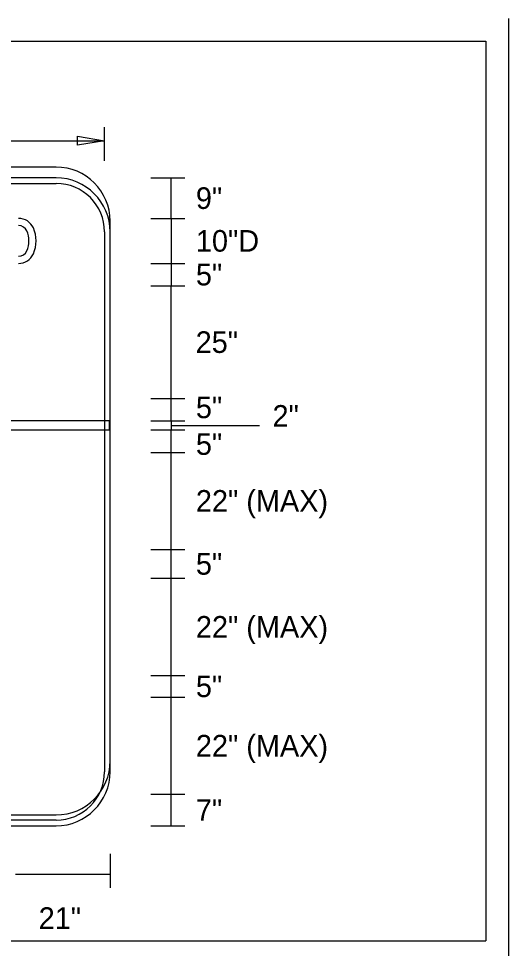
# Model space of a CAD drawing. Extents: x 10268259 to 10268554, y 2141099 to 2141249.
# Drawn here: x 10268378.4 to 10268394.73, y 2141173.28 to 2141204.28 of the extents above; entities that cross this region are included whole.
import ezdxf

# ---------------------------------------------------------------- set-up
doc = ezdxf.new("R2010")
doc.units = 0
for name, color, linetype in [('56', 7, 'Continuous'), ('60', 7, 'Continuous'), ('GSColorFill', 7, 'Continuous'), ('GSDims', 7, 'Continuous'), ('Level 54', 7, 'Continuous'), ('SheetBorder_dp', 7, 'Continuous')]:
    doc.layers.add(name, color=color, linetype=linetype)

msp = doc.modelspace()

# ---------------------------------------------------------------- linework, layer by layer
at = {"layer": '56'}
for p, q in [((10268381.427, 2141190.868), (10268354.48, 2141190.868)), ((10268381.427, 2141190.868), (10268354.48, 2141190.868)), ((10268381.427, 2141190.868), (10268354.48, 2141190.868)), ((10268381.427, 2141190.569), (10268381.427, 2141190.868)), ((10268381.427, 2141190.569), (10268381.427, 2141190.868)), ((10268381.427, 2141190.569), (10268381.427, 2141190.868)), ((10268354.48, 2141190.569), (10268381.427, 2141190.569)), ((10268354.48, 2141190.569), (10268381.427, 2141190.569)), ((10268354.48, 2141190.569), (10268381.427, 2141190.569))]:
    msp.add_line(p, q, dxfattribs=at)
for centre, major_axis, start_param, end_param in [((10268378.397, 2141197.078), (0, 0.54), 5.13024, 6.283185), ((10268378.397, 2141197.078), (0, 0.54), 5.13024, 6.283185), ((10268378.397, 2141197.078), (0, 0.54), 5.13024, 6.283185), ((10268378.397, 2141197.078), (0, 0.3), 5.13024, 6.283185), ((10268378.397, 2141197.078), (0, 0.3), 5.13024, 6.283185), ((10268378.397, 2141197.078), (0, 0.3), 5.13024, 6.283185), ((10268377.924, 2141196.868), (0, 1.058), 4.294538, 5.13024), ((10268377.924, 2141196.868), (0, 1.058), 4.294538, 5.13024), ((10268377.924, 2141196.868), (0, 1.058), 4.294538, 5.13024), ((10268377.924, 2141196.868), (0, 0.818), 4.294538, 5.13024), ((10268377.924, 2141196.868), (0, 0.818), 4.294538, 5.13024), ((10268377.924, 2141196.868), (0, 0.818), 4.294538, 5.13024), ((10268378.397, 2141196.658), (0, 0.3), 3.141593, 4.294538), ((10268378.397, 2141196.658), (0, 0.3), 3.141593, 4.294538), ((10268378.397, 2141196.658), (0, 0.3), 3.141593, 4.294538), ((10268378.397, 2141196.658), (0, 0.54), 3.141593, 4.294538), ((10268378.397, 2141196.658), (0, 0.54), 3.141593, 4.294538), ((10268378.397, 2141196.658), (0, 0.54), 3.141593, 4.294538)]:
    msp.add_ellipse(centre, major_axis=major_axis, ratio=0.999993, start_param=start_param, end_param=end_param, dxfattribs=at)
at = {"layer": '60'}
for p, q in [((10268341.73, 2141203.528), (10268393.98, 2141203.528)), ((10268393.98, 2141203.528), (10268393.98, 2141173.528)), ((10268341.73, 2141173.528), (10268393.98, 2141173.528))]:
    msp.add_line(p, q, dxfattribs=at)
at = {"layer": 'GSColorFill'}
for p, q in [((10268379.649, 2141199.328), (10268356.249, 2141199.328)), ((10268381.449, 2141179.528), (10268381.449, 2141197.528)), ((10268356.249, 2141177.728), (10268379.649, 2141177.728))]:
    msp.add_line(p, q, dxfattribs=at)
for centre, start, end in [((10268379.649, 2141197.528), 0, 90), ((10268379.649, 2141179.528), 270, 0)]:
    msp.add_arc(centre, 1.8, start, end, dxfattribs=at)
at = {"layer": 'GSDims'}
for p, q in [((10268381.261, 2141199.532), (10268381.261, 2141200.657)), ((10268354.449, 2141200.207), (10268381.261, 2141200.207)), ((10268382.812, 2141198.968), (10268383.937, 2141198.968)), ((10268383.487, 2141197.618), (10268383.487, 2141198.968)), ((10268382.812, 2141197.618), (10268383.937, 2141197.618)), ((10268383.487, 2141197.618), (10268383.487, 2141196.118)), ((10268382.812, 2141196.118), (10268383.937, 2141196.118)), ((10268383.487, 2141196.118), (10268383.487, 2141195.368)), ((10268382.812, 2141195.368), (10268383.937, 2141195.368)), ((10268383.487, 2141191.617), (10268383.487, 2141195.368)), ((10268382.812, 2141191.617), (10268383.937, 2141191.617)), ((10268383.487, 2141190.867), (10268383.487, 2141191.617)), ((10268382.812, 2141190.867), (10268383.937, 2141190.867)), ((10268383.487, 2141190.867), (10268383.487, 2141190.567)), ((10268383.487, 2141190.717), (10268386.426, 2141190.717)), ((10268382.812, 2141190.567), (10268383.937, 2141190.567)), ((10268383.487, 2141189.817), (10268383.487, 2141190.567)), ((10268382.812, 2141189.817), (10268383.937, 2141189.817)), ((10268383.487, 2141186.58), (10268383.487, 2141189.817)), ((10268382.812, 2141186.58), (10268383.937, 2141186.58)), ((10268383.487, 2141185.617), (10268383.487, 2141186.58)), ((10268382.812, 2141185.617), (10268383.937, 2141185.617)), ((10268383.487, 2141182.38), (10268383.487, 2141185.617)), ((10268382.812, 2141182.38), (10268383.937, 2141182.38)), ((10268383.487, 2141181.655), (10268383.487, 2141182.38)), ((10268382.812, 2141181.655), (10268383.937, 2141181.655)), ((10268383.487, 2141178.417), (10268383.487, 2141181.655)), ((10268382.812, 2141178.417), (10268383.937, 2141178.417)), ((10268383.487, 2141177.367), (10268383.487, 2141178.417)), ((10268382.812, 2141177.367), (10268383.937, 2141177.367)), ((10268381.449, 2141176.428), (10268381.449, 2141175.303)), ((10268378.299, 2141175.753), (10268381.449, 2141175.753))]:
    msp.add_line(p, q, dxfattribs=at)
msp.add_lwpolyline([(10268381.261, 2141200.207), (10268380.361, 2141200.057), (10268380.361, 2141200.357)], close=True, dxfattribs=at)
at = {"layer": 'Level 54'}
for p, q in [((10268379.649, 2141198.968), (10268356.249, 2141198.968)), ((10268356.249, 2141198.78), (10268379.649, 2141198.78)), ((10268381.261, 2141197.168), (10268381.261, 2141179.167)), ((10268381.449, 2141179.167), (10268381.449, 2141197.168)), ((10268379.649, 2141177.555), (10268356.251, 2141177.555)), ((10268356.251, 2141177.367), (10268379.649, 2141177.367))]:
    msp.add_line(p, q, dxfattribs=at)
for centre, radius, start, end in [((10268379.649, 2141197.168), 1.8, 0, 90), ((10268379.649, 2141197.168), 1.613, 0, 90), ((10268379.649, 2141179.167), 1.8, 270, 0), ((10268379.649, 2141179.167), 1.613, 270, 0)]:
    msp.add_arc(centre, radius, start, end, dxfattribs=at)
at = {"layer": 'SheetBorder_dp'}
msp.add_line((10268394.73, 2141204.278), (10268394.73, 2141108.278), dxfattribs=at)

# ---------------------------------------------------------------- texts
at = {"layer": 'GSDims'}
for s, p in [('9"', (10268384.309, 2141197.933)), ('10"D', (10268384.309, 2141196.508)), ('5"', (10268384.309, 2141195.383)), ('25"', (10268384.301, 2141193.132)), ('5"', (10268384.309, 2141190.957)), ('2"', (10268386.865, 2141190.672)), ('5"', (10268384.309, 2141189.734)), ('22" (MAX)', (10268384.309, 2141187.839)), ('5"', (10268384.309, 2141185.739)), ('22" (MAX)', (10268384.309, 2141183.639)), ('5"', (10268384.309, 2141181.657)), ('22" (MAX)', (10268384.309, 2141179.676)), ('7"', (10268384.309, 2141177.532)), ('21"', (10268379.067, 2141173.929))]:
    msp.add_text(s, height=0.72, dxfattribs=at).set_placement(p)

doc.saveas('drawing.dxf')
